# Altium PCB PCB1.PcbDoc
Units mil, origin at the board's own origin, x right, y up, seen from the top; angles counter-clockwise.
Board outline 2700 x 2100 mil, 2 copper layers (Top Layer, Bottom Layer); 10 components, 29 nets, 378 pads, 17 vias.
Unrouted connection lines stored in the file: 1.
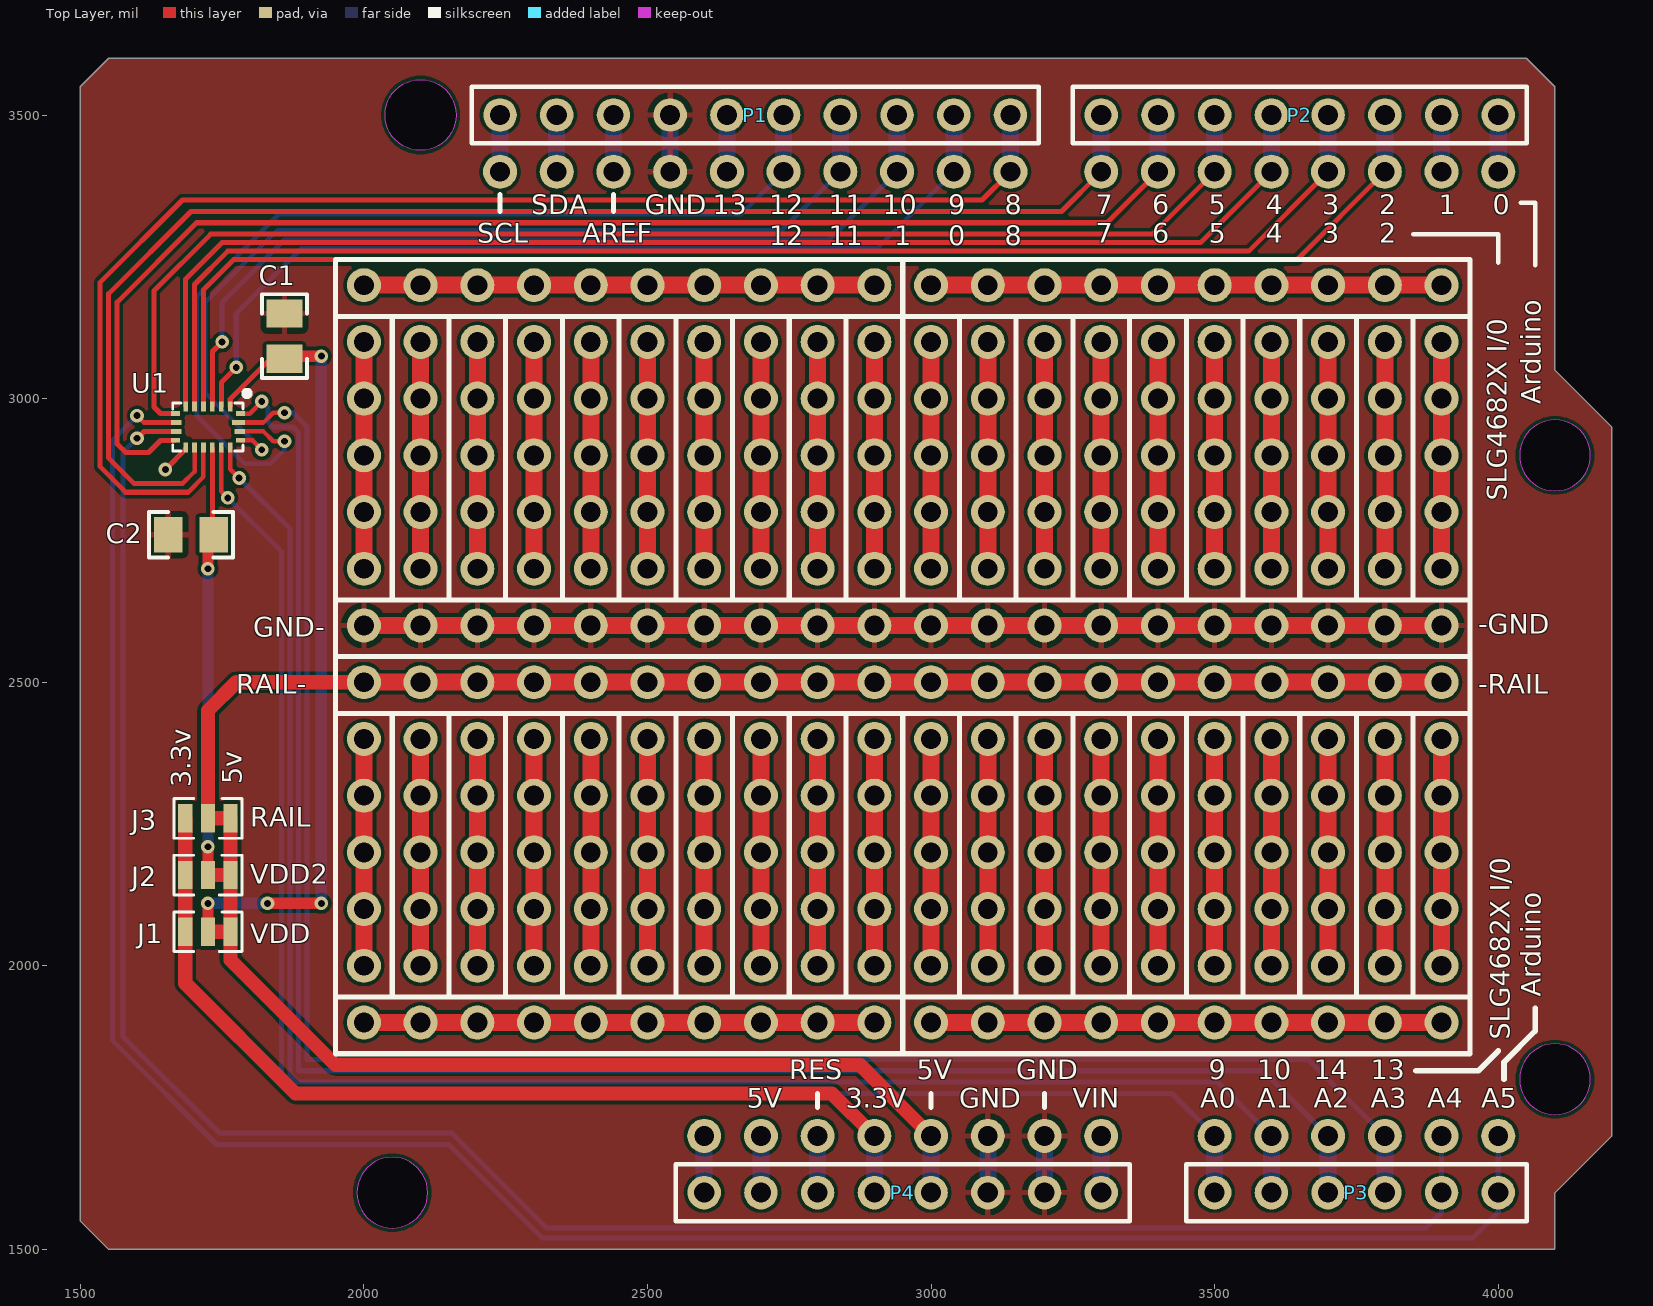
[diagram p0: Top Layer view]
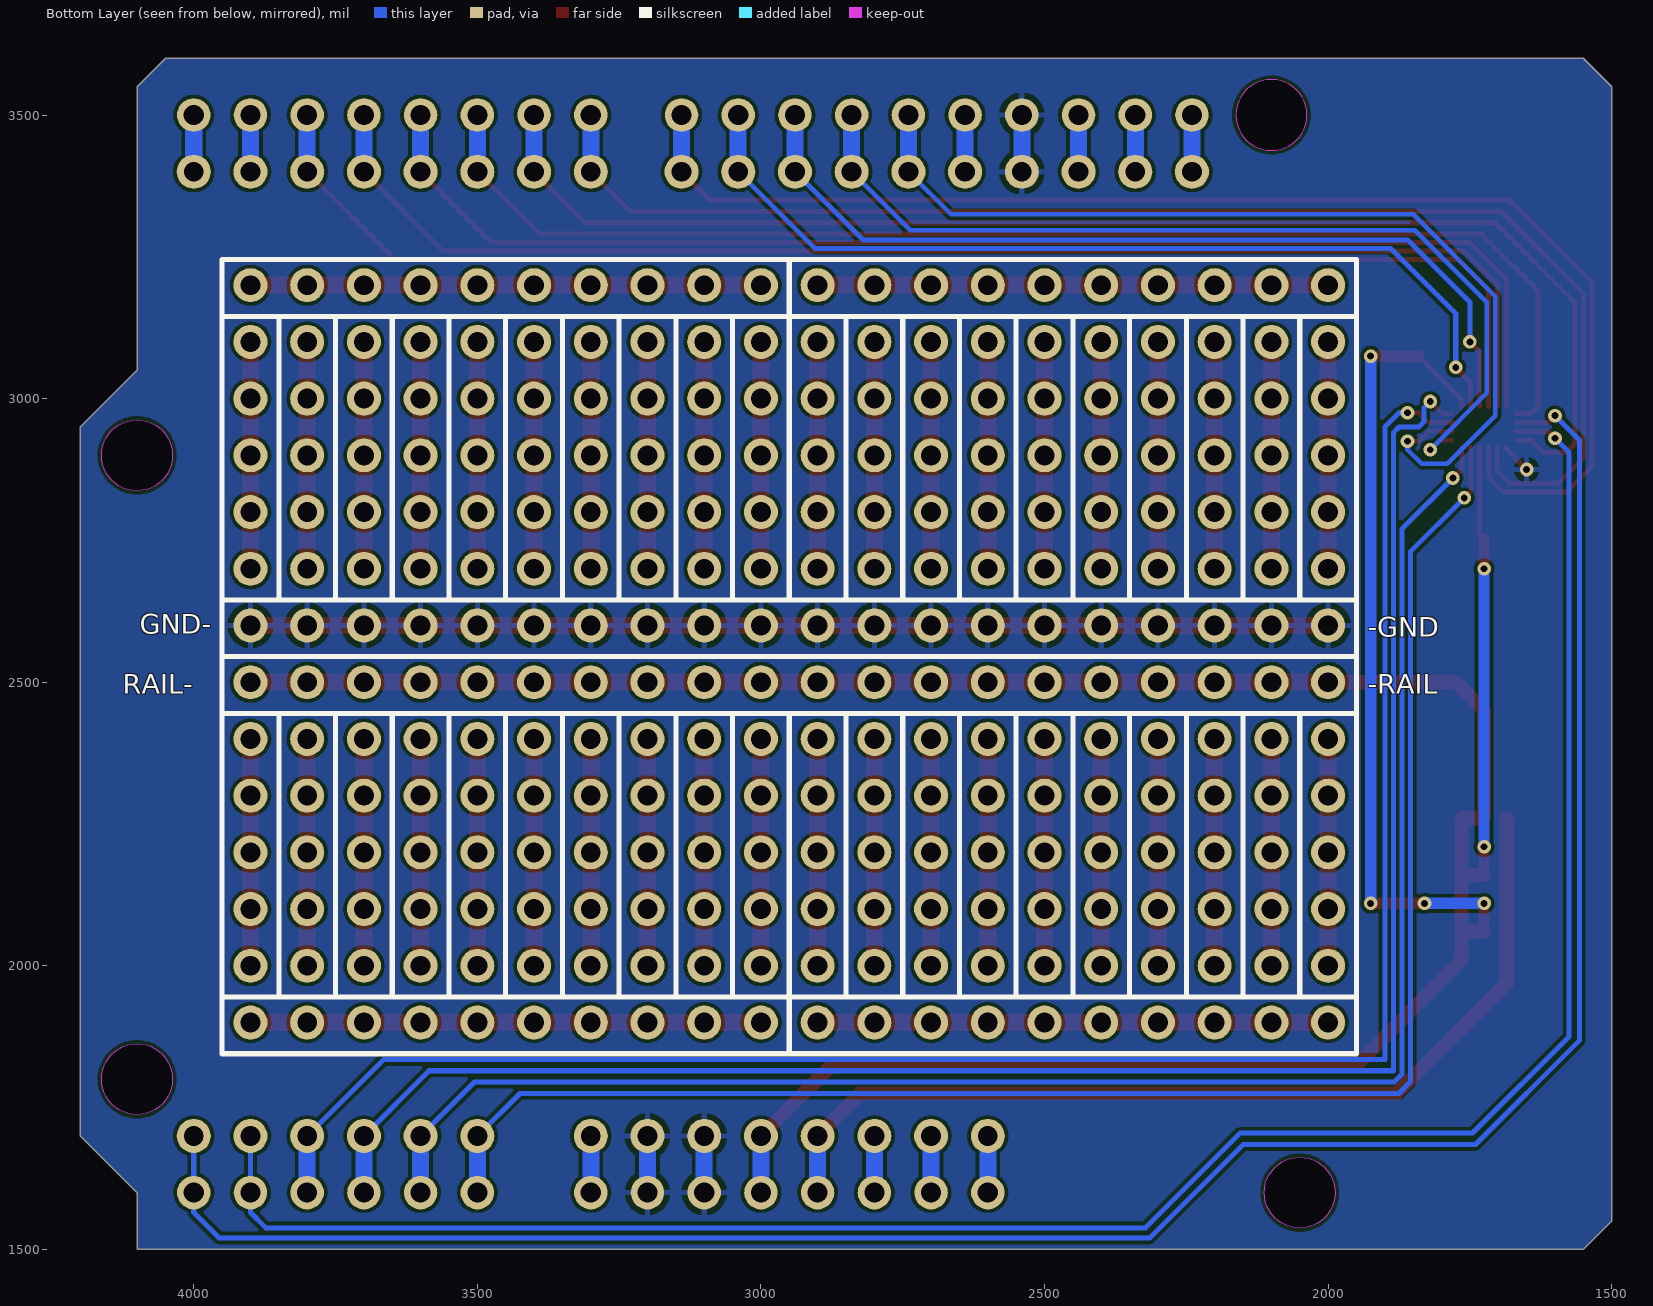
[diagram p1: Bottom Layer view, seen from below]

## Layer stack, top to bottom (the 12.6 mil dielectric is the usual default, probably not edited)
Top Solder: solder mask 0.4, Solder Resist, Dk 3.5
Top Layer: signal copper 1.4
Dielectric 1: dielectric 12.6, FR-4, Dk 4.8
Bottom Layer: signal copper 1.4
Bottom Solder: solder mask 0.4, Solder Resist, Dk 3.5

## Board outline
1550,1500 1500,1550 1500,3550 1550,3600 4050,3600 4100,3550 4100,3050 4200,2950 4200,1700 4100,1600 4100,1500
cut-out: 4037.5,1800 ccw(c4100,1800) 4100,1737.5 ccw(c4100,1800) 4162.5,1800 ccw(c4100,1800) 4100,1862.5 ccw(c4100,1800)
cut-out: 4037.5,2900 ccw(c4100,2900) 4100,2837.5 ccw(c4100,2900) 4162.5,2900 ccw(c4100,2900) 4100,2962.5 ccw(c4100,2900)
cut-out: 2100,3437.5 cw(c2100,3500) 2037.5,3500 cw(c2100,3500) 2100,3562.5 cw(c2100,3500) 2162.5,3500 cw(c2100,3500)
cut-out: 1987.5,1600 ccw(c2050,1600) 2050,1537.5 ccw(c2050,1600) 2112.5,1600 ccw(c2050,1600) 2050,1662.5 ccw(c2050,1600)

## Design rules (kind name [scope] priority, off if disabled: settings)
Clearance [All] p1: gap=6 ignorepadtopadclearanceinfootprint=FALSE
PolygonConnect [All] p1: connectstyle=Relief reliefconductorwidth=10 reliefentries=4 polygonreliefangle="90 Angle" airgapwidth=10
RoutingVias [All] p1: holewidth=12 width=24 viastyle="Through Hole" minholewidth=12 minwidth=24 maxholewidth=300 maxwidth=400
SolderMaskExpansion [All] p1: expansion=4
Width [All] p1: maxlimit=50 minlimit=6 preferedwidth=10
30 further rules are at their usual default settings.

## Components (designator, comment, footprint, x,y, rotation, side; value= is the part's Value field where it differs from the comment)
C1 "C2012X5R1H104M085AA" 0805_HV 1860,3110 r90 top value=0.1uF
C2 "C2012X5R1H104M085AA" 0805_HV 1695,2760 r180 top value=0.1uF
J1 "Jumper" JUMPER 1725,2060 r0 top net-tie
J2 "Jumper" JUMPER 1725,2160 r0 top net-tie
J3 "Jumper" JUMPER 1725,2260 r0 top net-tie
P1 "Header 10" HDR1X10 3140,3500 r180 top locked
P2 "Header 8" HDR1X8 4000,3500 r180 top locked
P3 "Header 6" HDR1X6 3500,1600 r0 top locked
P4 "Header 8" HDR1X8 2600,1600 r0 top locked
U1 "Component_1" STQFN 1725,2950 r270 top

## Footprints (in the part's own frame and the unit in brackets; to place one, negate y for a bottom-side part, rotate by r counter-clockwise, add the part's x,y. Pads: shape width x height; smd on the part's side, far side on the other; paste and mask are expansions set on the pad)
0805_HV [mil] "0805 with 30mil clearance between pads"
  rect 50x63 smd: 1(-40,0) 2(40,0)
  silkscreen extent -74,-40 74,40, body extent -43,-29 43,29, height 57
HDR1X6 [mm] "Connector; Header; 6 Position"
  round 1.5 hole 0.9: 1(0,0) 2(2.54,0) 3(5.08,0) 4(7.62,0) 5(10.16,0) 6(12.7,0)
  silkscreen extent -1.27,-1.27 13.97,1.27
HDR1X8 [mm] "Connector; Header; 8 Position"
  round 1.5 hole 0.9: 1(0,0) 2(2.54,0) 3(5.08,0) 4(7.62,0) 5(10.16,0) 6(12.7,0) 7(15.24,0) 8(17.78,0)
  silkscreen extent -1.27,-1.27 19.05,1.27
HDR1X10 [mm] "Connector; Header; 10 Position"
  round 1.5 hole 0.9: 1(0,0) 2(2.54,0) 3(5.08,0) 4(7.62,0) 5(10.16,0) 6(12.7,0) 7(15.24,0) 8(17.78,0) 9(20.32,0) 10(22.86,0)
  silkscreen extent -1.27,-1.27 24.13,1.27
JUMPER [mil]
  rect 25x50 smd: 1(-40,0) 2(0,0) 3(40,0)
  Top Layer lines w25: 0,0 40,0
  silkscreen extent -60,-35 60,35
STQFN [mm] "PACKAGE OUTLINES FOR STQFN 20L 2 MM X 3 MM 0.4P FCD"
  rect 0.465x0.21 smd: 1(-0.917,1) 2(-0.917,0.6) 3(-0.918,0.2) 4(-0.918,-0.2) 5(-0.917,-0.6) 6(-0.917,-1) 11(0.917,-1) 12(0.917,-0.6) 13(0.918,-0.2) 14(0.918,0.2) 15(0.917,0.6) 16(0.917,1)
  rect 0.21x0.39 smd: 7(-0.6,-1.455) 10(0.6,-1.455) 17(0.6,1.455) 20(-0.6,1.455)
  rect 0.21x0.465 smd: 8(-0.2,-1.418) 9(0.2,-1.418) 18(0.2,1.418)
  rect 0.21x0.565 smd: 19(-0.2,1.368)
  silkscreen extent -1.63,-1.58 1.07,1.88, body extent -1,-1.5 1,1.5, height 0.55

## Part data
C1 C2: "CAP, CERM, 0.1 µF, 50 V, +/- 20%, X5R, 0805", Cap_Case=0805, Manufacturer=TDK, Supplier Part Number 1=445-10548-1-ND, TempCo=X5R, Tolerance_%=20, Value1="0.02619 ohm", Value2=50V, ValueDisplayed=0.1µF
P1: "Header, 10-Pin"
P2 P4: "Header, 8-Pin"
P3: "Header, 6-Pin"

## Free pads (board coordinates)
  round 60 hole 35: ""(2000,1900) ""(2000,2000) ""(2000,2100) ""(2000,2200) ""(2000,2300) ""(2000,2400) ""(2000,2500) ""(2000,2600) ""(2000,2700) ""(2000,2800) ""(2000,2900) ""(2000,3000) ""(2000,3100) ""(2000,3200) ""(2100,1900) ""(2100,2000) ""(2100,2100) ""(2100,2200) ""(2100,2300) ""(2100,2400) ""(2100,2500) ""(2100,2600) ""(2100,2700) ""(2100,2800) ""(2100,2900) ""(2100,3000) ""(2100,3100) ""(2100,3200) ""(2200,1900) ""(2200,2000) ""(2200,2100) ""(2200,2200) ""(2200,2300) ""(2200,2400) ""(2200,2500) ""(2200,2600) ""(2200,2700) ""(2200,2800) ""(2200,2900) ""(2200,3000) ""(2200,3100) ""(2200,3200) ""(2240,3400) ""(2300,1900) ""(2300,2000) ""(2300,2100) ""(2300,2200) ""(2300,2300) ""(2300,2400) ""(2300,2500) ""(2300,2600) ""(2300,2700) ""(2300,2800) ""(2300,2900) ""(2300,3000) ""(2300,3100) ""(2300,3200) ""(2340,3400) ""(2400,1900) ""(2400,2000) ""(2400,2100) ""(2400,2200) ""(2400,2300) ""(2400,2400) ""(2400,2500) ""(2400,2600) ""(2400,2700) ""(2400,2800) ""(2400,2900) ""(2400,3000) ""(2400,3100) ""(2400,3200) ""(2440,3400) ""(2500,1900) ""(2500,2000) ""(2500,2100) ""(2500,2200) ""(2500,2300) ""(2500,2400) ""(2500,2500) ""(2500,2600) ""(2500,2700) ""(2500,2800) ""(2500,2900) ""(2500,3000) ""(2500,3100) ""(2500,3200) ""(2540,3400) ""(2600,1700) ""(2600,1900) ""(2600,2000) ""(2600,2100) ""(2600,2200) ""(2600,2300) ""(2600,2400) ""(2600,2500) ""(2600,2600) ""(2600,2700) ""(2600,2800) ""(2600,2900) ""(2600,3000) ""(2600,3100) ""(2600,3200) ""(2640,3400) ""(2700,1700) ""(2700,1900) ""(2700,2000) ""(2700,2100) ""(2700,2200) ""(2700,2300) ""(2700,2400) ""(2700,2500) ""(2700,2600) ""(2700,2700) ""(2700,2800) ""(2700,2900) ""(2700,3000) ""(2700,3100) ""(2700,3200) ""(2740,3400) ""(2800,1700) ""(2800,1900) ""(2800,2000) ""(2800,2100) ""(2800,2200) ""(2800,2300) ""(2800,2400) ""(2800,2500) ""(2800,2600) ""(2800,2700) ""(2800,2800) ""(2800,2900) ""(2800,3000) ""(2800,3100) ""(2800,3200) ""(2840,3400) ""(2900,1700) ""(2900,1900) ""(2900,2000) ""(2900,2100) ""(2900,2200) ""(2900,2300) ""(2900,2400) ""(2900,2500) ""(2900,2600) ""(2900,2700) ""(2900,2800) ""(2900,2900) ""(2900,3000) ""(2900,3100) ""(2900,3200) ""(2940,3400) ""(3000,1700) ""(3000,1900) ""(3000,1900) ""(3000,2000) ""(3000,2100) ""(3000,2200) ""(3000,2300) ""(3000,2400) ""(3000,2500) ""(3000,2600) ""(3000,2700) ""(3000,2800) ""(3000,2900) ""(3000,3000) ""(3000,3100) ""(3000,3200) ""(3040,3400) ""(3100,1700) ""(3100,1900) ""(3100,2000) ""(3100,2100) ""(3100,2200) ""(3100,2300) ""(3100,2400) ""(3100,2500) ""(3100,2600) ""(3100,2700) ""(3100,2800) ""(3100,2900) ""(3100,3000) ""(3100,3100) ""(3100,3200) ""(3140,3400) ""(3200,1700) ""(3200,1900) ""(3200,2000) ""(3200,2100) ""(3200,2200) ""(3200,2300) ""(3200,2400) ""(3200,2500) ""(3200,2600) ""(3200,2700) ""(3200,2800) ""(3200,2900) ""(3200,3000) ""(3200,3100) ""(3200,3200) ""(3300,1700) ""(3300,1900) ""(3300,2000) ""(3300,2100) ""(3300,2200) ""(3300,2300) ""(3300,2400) ""(3300,2500) ""(3300,2600) ""(3300,2700) ""(3300,2800) ""(3300,2900) ""(3300,3000) ""(3300,3100) ""(3300,3200) ""(3300,3400) ""(3400,1900) ""(3400,2000) ""(3400,2100) ""(3400,2200) ""(3400,2300) ""(3400,2400) ""(3400,2500) ""(3400,2600) ""(3400,2700) ""(3400,2800) ""(3400,2900) ""(3400,3000) ""(3400,3100) ""(3400,3200) ""(3400,3400) ""(3500,1700) ""(3500,1900) ""(3500,2000) ""(3500,2100) ""(3500,2200) ""(3500,2300) ""(3500,2400) ""(3500,2500) ""(3500,2600) ""(3500,2700) ""(3500,2800) ""(3500,2900) ""(3500,3000) ""(3500,3100) ""(3500,3200) ""(3500,3400) ""(3600,1700) ""(3600,1900) ""(3600,2000) ""(3600,2100) ""(3600,2200) ""(3600,2300) ""(3600,2400) ""(3600,2500) ""(3600,2600) ""(3600,2700) ""(3600,2800) ""(3600,2900) ""(3600,3000) ""(3600,3100) ""(3600,3200) ""(3600,3400) ""(3700,1700) ""(3700,1900) ""(3700,2000) ""(3700,2100) ""(3700,2200) ""(3700,2300) ""(3700,2400) ""(3700,2500) ""(3700,2600) ""(3700,2700) ""(3700,2800) ""(3700,2900) ""(3700,3000) ""(3700,3100) ""(3700,3200) ""(3700,3400) ""(3800,1700) ""(3800,1900) ""(3800,2000) ""(3800,2100) ""(3800,2200) ""(3800,2300) ""(3800,2400) ""(3800,2500) ""(3800,2600) ""(3800,2700) ""(3800,2800) ""(3800,2900) ""(3800,3000) ""(3800,3100) ""(3800,3200) ""(3800,3400) ""(3900,1700) ""(3900,1900) ""(3900,2000) ""(3900,2100) ""(3900,2200) ""(3900,2300) ""(3900,2400) ""(3900,2500) ""(3900,2600) ""(3900,2700) ""(3900,2800) ""(3900,2900) ""(3900,3000) ""(3900,3100) ""(3900,3200) ""(3900,3400) ""(4000,1700) ""(4000,3400)

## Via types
v1: diameter 24, hole 12, Top Layer to Bottom Layer, tented both sides, 17 vias

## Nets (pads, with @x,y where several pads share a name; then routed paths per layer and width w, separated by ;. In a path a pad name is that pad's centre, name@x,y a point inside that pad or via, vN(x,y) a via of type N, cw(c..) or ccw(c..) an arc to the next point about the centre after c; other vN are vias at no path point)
3.3V: J1.1 J2.1 J3.1 P4.4 pad.@2900,1700 | length 1717.3
  Top Layer w25: J3.1 1685,2200 J2.1 J1.1 1685,1969.29 1879.29,1775 2825,1775 pad.@2900,1700
  Bottom Layer w30: P4.4 pad.@2900,1700
5V: J1.3 J2.3 J3.3 P4.2 P4.5 pad.@2700,1700 pad.@3000,1700 | length 1813.4
  Top Layer w25: J3.3 1765,2200 J2.3 J1.3 1765,2010 1950,1825 2875,1825 pad.@3000,1700
  Bottom Layer w30: P4.2 pad.@2700,1700 ; P4.5 pad.@3000,1700
AD0: P3.1 pad.@3500,1700 U1.15 | length 2947.3
  Top Layer w8: U1.15 1748.62,2836.38 v1(1760,2825)
  Bottom Layer w9: v1(1760,2825) 1855,2730 1855,1795 1875,1775 3425,1775 pad.@3500,1700
  Bottom Layer w30: P3.1 pad.@3500,1700
AD1: P3.2 pad.@3600,1700 U1.16 | length 3024.2
  Top Layer w8: U1.16 1764.37,2875.63 v1(1780,2860)
  Bottom Layer w9: v1(1780,2860) 1870,2770 1870,1808.28 1883.28,1795 3505,1795 pad.@3600,1700
  Bottom Layer w30: P3.2 pad.@3600,1700
AD2: P3.3 pad.@3700,1700 U1.20 | length 3239.5
  Top Layer w8: U1.20 1798.62,2973.62 v1(1820,2995)
  Bottom Layer w9: v1@1815,2990 1825,2990 1831.25,2983.75 1831.25,2958.75 1840,2950 1875,2950 1885,2940 1885,1815 3585,1815 pad.@3700,1700
  Bottom Layer w30: P3.3 pad.@3700,1700
AD3: P3.4 pad.@3800,1700 U1.19 | length 3309.6
  Top Layer w8: U1.19 1822.87,2957.87 1840,2975 v1(1860,2975)
  Bottom Layer w9: v1(1860,2975) 1875,2975 1900,2950 1900,1834.85 3665.15,1834.85 pad.@3800,1700
  Bottom Layer w30: P3.4 pad.@3800,1700
AD4/SDA: P3.5 pad.@3900,1700 U1.9 | length 3750.1
  Top Layer w9: v1(1600,2930) 1612.13,2942.13 U1.9
  Bottom Layer w9: v1(1600,2930) 1575,2905 1575,1875.46 1745.46,1705 2155,1705 2322,1538 3873,1538 3900,1565 P3.5 pad.@3900,1700
AD5/SCL: P3.6 pad.@4000,1700 U1.8 | length 3934.8
  Top Layer w8: v1(1600,2970) 1612.13,2957.87 U1.8
  Bottom Layer w9: v1(1600,2970) 1557,2927 1557,1868 1740,1685 2149.54,1685 2314.54,1520 3955,1520 4000,1565 P3.6 pad.@4000,1700
AREF: P1.8 pad.@2440,3400 | length 100
  Bottom Layer w30: pad.@2440,3400 P1.8
BreakOutRail: J3.2 pad.@2000,2500 pad.@2100,2500 pad.@2200,2500 pad.@2300,2500 pad.@2400,2500 pad.@2500,2500 pad.@2600,2500 pad.@2700,2500 pad.@2800,2500 pad.@2900,2500 pad.@3000,2500 pad.@3100,2500 pad.@3200,2500 pad.@3300,2500 pad.@3400,2500 pad.@3500,2500 pad.@3600,2500 pad.@3700,2500 pad.@3800,2500 pad.@3900,2500 | length 2385.7
  Top Layer w25: J3.2 1725,2450 1775,2500 pad.@2000,2500
  Top Layer w30: pad.@2000,2500 2100,2500 2200,2500 2300,2500 2400,2500 2500,2500 2600,2500 2700,2500 2800,2500 2900,2500 3000,2500 3100,2500 3200,2500 3300,2500 3400,2500 3500,2500 3600,2500 3700,2500 3800,2500 pad.@3900,2500
GND: C1.2 C2.2 P1.7 P4.6 P4.7 pad.@2000,2600 pad.@2100,2600 pad.@2200,2600 pad.@2300,2600 pad.@2400,2600 pad.@2500,2600 pad.@2540,3400 pad.@2600,2600 pad.@2700,2600 pad.@2800,2600 pad.@2900,2600 pad.@3000,2600 pad.@3100,1700 pad.@3100,2600 pad.@3200,1700 pad.@3200,2600 pad.@3300,2600 pad.@3400,2600 pad.@3500,2600 pad.@3600,2600 pad.@3700,2600 pad.@3800,2600 pad.@3900,2600 U1.11 | length 2253.6
  Top Layer w9: v1(1650,2875) 1685.63,2910.63 U1.11
  Top Layer w30: pad.@2000,2600 2100,2600 2200,2600 2300,2600 2400,2600 2500,2600 2600,2600 2700,2600 2800,2600 2900,2600 3000,2600 3100,2600 3200,2600 3300,2600 3400,2600 3500,2600 3600,2600 3700,2600 3800,2600 pad.@3900,2600
  Bottom Layer w30: pad.@2540,3400 P1.7 ; P4.6 pad.@3100,1700 ; P4.7 pad.@3200,1700
IO2: P2.3 pad.@3800,3400 U1.4 | length 2475
  Top Layer w9: U1.4 1717.13,3192.13 1770,3245 3645,3245 pad.@3800,3400
  Bottom Layer w30: pad.@3800,3400 P2.3
IO3: P2.4 pad.@3700,3400 U1.5 | length 2396.1
  Top Layer w9: U1.5 1701.38,3201.38 1760,3260 3560,3260 pad.@3700,3400
  Bottom Layer w30: pad.@3700,3400 P2.4
IO4: P2.5 pad.@3600,3400 U1.6 | length 2317.3
  Top Layer w9: U1.6 1685.63,3210.63 1750,3275 3475,3275 pad.@3600,3400
  Bottom Layer w30: pad.@3600,3400 P2.5
IO5: P2.6 pad.@3500,3400 U1.7 | length 2304.4
  Top Layer w9: U1.7 1641.38,2973.62 1630,2985 1630,3190 1730,3290 3390,3290 pad.@3500,3400
  Bottom Layer w30: pad.@3500,3400 P2.6
IO6: P2.7 pad.@3400,3400 U1.10 | length 2398.1
  Top Layer w9: U1.10 1641.38,2926.38 1620,2905 1580,2905 1565,2920 1565,3170 1705,3310 3310,3310 pad.@3400,3400
  Bottom Layer w30: pad.@3400,3400 P2.7
IO7: P2.8 pad.@3300,3400 U1.12 | length 2450.4
  Top Layer w8: 1680,2850 1701.38,2871.38 U1.12
  Top Layer w9: 1680,2850 1595,2850 1550,2895 1550,3185 1695,3330 3230,3330 pad.@3300,3400
  Bottom Layer w30: pad.@3300,3400 P2.8
IO8: P1.1 pad.@3140,3400 U1.13 | length 2374.5
  Top Layer w8: 1690,2835 1717.13,2862.13 U1.13
  Top Layer w9: 1690,2835 1580,2835 1535,2880 1535,3205 1680,3350 3090,3350 pad.@3140,3400
  Bottom Layer w30: pad.@3140,3400 P1.1
IO9: P1.2 pad.@3040,3400 U1.2 | length 1643.4
  Top Layer w9: U1.2 1748.62,3028.62 v1(1775,3055)
  Bottom Layer w9: v1(1775,3055) 1775,3150 1890,3265 2905,3265 pad.@3040,3400
  Bottom Layer w30: pad.@3040,3400 P1.2
MISO/IO12: P1.5 pad.@2740,3400 U1.18 | length 1738
  Top Layer w8: U1.18 1822.87,2942.13 1840,2925 v1(1860,2925)
  Bottom Layer w8: v1(1860,2925) 1860,2910 1835,2885 1790,2885 1705,2970 1705,3180 1850,3325 2665,3325 pad.@2740,3400
  Bottom Layer w30: pad.@2740,3400 P1.5
MOSI/IO11: P1.4 pad.@2840,3400 U1.17 | length 1661.2
  Top Layer w8: U1.17 1803.62,2926.38 v1(1820,2910)
  Bottom Layer w8: v1(1820,2910) 1720,3010 1720,3170 1847,3297 2737,3297 pad.@2840,3400
  Bottom Layer w30: pad.@2840,3400 P1.4
NetC1_1: C1.1 J1.2 U1.1 | length 1420.2
  Top Layer w9: U1.1 1764.37,2999.37 C1.1@1840,3075
  Top Layer w20: J1.2 v1(1725,2110) ; v1(1830,2110) v1(1925,2110) ; C1.1@1840,3075 v1(1925,3075)
  Bottom Layer w20: v1(1725,2110) v1(1830,2110) ; v1(1925,2110) v1(1925,3075)
NetC2_1: C2.1 J2.2 U1.14 | length 757.1
  Top Layer w9: C2.1@1725,2752.13 1732.87,2760 U1.14
  Top Layer w20: J2.2 v1(1725,2210) ; v1(1725,2700) C2.1@1725,2752.13
  Bottom Layer w20: v1(1725,2210) v1(1725,2700)
RESET: P4.3 pad.@2800,1700 | length 100
  Bottom Layer w30: P4.3 pad.@2800,1700
RX/IO0: P2.1 pad.@4000,3400 | length 100
  Bottom Layer w30: pad.@4000,3400 P2.1
SCK/IO13: P1.6 pad.@2640,3400 | length 100
  Bottom Layer w30: pad.@2640,3400 P1.6
SS/IO10: P1.3 pad.@2940,3400 U1.3 | length 1576.2
  Top Layer w9: U1.3 1732.87,3082.87 v1(1750,3100)
  Bottom Layer w9: v1(1750,3100) 1750,3170 1860,3280 2820,3280 pad.@2940,3400
  Bottom Layer w30: pad.@2940,3400 P1.3
TX/IO1: P2.2 pad.@3900,3400 | length 100
  Bottom Layer w30: pad.@3900,3400 P2.2
Vin: P4.8 pad.@3300,1700 | length 100
  Bottom Layer w30: P4.8 pad.@3300,1700
pads on no net: P1.9 P1.10 P4.1
copper on no net: | length 19900
  Top Layer w30: 2000,1900 2900,1900 ; 2000,2000 2000,2400 ; 2000,2700 2000,3100 ; 2000,3200 2900,3200 ; 2100,2000 2100,2400 ; 2100,2700 2100,3100 ; 2200,2000 2200,2400 ; 2200,2700 2200,3100 ; 2300,2000 2300,2400 ; 2300,2700 2300,3100 ; 2400,2000 2400,2400 ; 2400,2700 2400,3100 ; 2500,2000 2500,2400 ; 2500,2700 2500,3100 ; 2600,2000 2600,2400 ; 2600,2700 2600,3100 ; 2700,2000 2700,2400 ; 2700,2700 2700,3100 ; 2800,2000 2800,2400 ; 2800,2700 2800,3100 ; 2900,2000 2900,2400 ; 2900,2700 2900,3100 ; 3000,1900 3900,1900 ; 3000,2000 3000,2400 ; 3000,2700 3000,3100 ; 3000,3200 3900,3200 ; 3100,2000 3100,2400 ; 3100,2700 3100,3100 ; 3200,2000 3200,2400 ; 3200,2700 3200,3100 ; 3300,2000 3300,2400 ; 3300,2700 3300,3100 ; 3400,2000 3400,2400 ; 3400,2700 3400,3100 ; 3500,2000 3500,2400 ; 3500,2700 3500,3100 ; 3600,2000 3600,2400 ; 3600,2700 3600,3100 ; 3700,2000 3700,2400 ; 3700,2700 3700,3100 ; 3800,2000 3800,2400 ; 3800,2700 3800,3100 ; 3900,2000 3900,2400 ; 3900,2700 3900,3100
  Bottom Layer w30: 2240,3400 2240,3500 ; 2340,3400 2340,3500 ; 2600,1600 2600,1700

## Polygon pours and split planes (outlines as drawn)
GND on Top Layer "Top Layer-gnd" (solid, pour order 0): 1550,1500 1500,1550 1500,3550 1550,3600 4050,3600 4100,3550 4100,3050 4200,2950 4200,1700 4100,1600 4100,1500
GND on Bottom Layer "bottom Layer-gnd" (solid, pour order 1): 1550,1500 1500,1550 1500,3550 1550,3600 4050,3600 4100,3550 4100,3050 4200,2950 4200,1700 4100,1600 4100,1500

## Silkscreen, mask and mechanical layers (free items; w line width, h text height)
Top Overlay:
  lines w8: 3850,3290 4000,3290 4000,3240 ; 4040,3345 4065,3345 4065,3235
  lines w9: 1950,1945 3950,1945 ; 1950,2445 3950,2445 ; 1950,2545 3950,2545 ; 1950,2645 3950,2645 ; 1950,3145 3950,3145 ; 2050,1945 2050,2445 ; 2050,2645 2050,3145 ; 2150,1945 2150,2445 ; 2150,2645 2150,3145 ; 2240,3330 2240,3360 ; 2250,1945 2250,2445 ; 2250,2645 2250,3145 ; 2350,1945 2350,2445 ; 2350,2645 2350,3145 ; 2440,3330 2440,3360 ; 2450,1945 2450,2445 ; 2450,2645 2450,3145 ; 2550,1945 2550,2445 ; 2550,2645 2550,3145 ; 2650,1945 2650,2445 ; 2650,2645 2650,3145 ; 2750,1945 2750,2445 ; 2750,2645 2750,3145 ; 2800,1750 2800,1775 ; 2850,1945 2850,2445 ; 2850,2645 2850,3145 ; 2950,1845 2950,2445 ; 2950,2645 2950,3245 ; 3000,1750 3000,1775 ; 3050,1945 3050,2445 ; 3050,2645 3050,3145 ; 3150,1945 3150,2445 ; 3150,2645 3150,3145 ; 3200,1750 3200,1775 ; 3250,1945 3250,2445 ; 3250,2645 3250,3145 ; 3350,1945 3350,2445 ; 3350,2645 3350,3145 ; 3450,1945 3450,2445 ; 3450,2645 3450,3145 ; 3550,1945 3550,2445 ; 3550,2645 3550,3145 ; 3650,1945 3650,2445 ; 3650,2645 3650,3145 ; 3750,1945 3750,2445 ; 3750,2645 3750,3145 ; 3850,1945 3850,2445 ; 3850,2645 3850,3145 ; 1950,1845 1950,3245 3950,3245 3950,1845 1950,1845
  lines w10: 3855,1815 3965,1815 4000,1850 ; 4010,1800 4010,1830 4065,1885 4065,1925
  text "SDA" at 2295,3325 h35
  text "GND" at 2495,3325 h35
  text "13" at 2615,3325 h35
  text "12" at 2715,3325 h35
  text "11" at 2820,3325 h35
  text "10" at 2915,3325 h35
  text "9" at 3030,3325 h35
  text "8" at 3130,3325 h35
  text "7" at 3290,3325 h35
  text "6" at 3390,3325 h35
  text "5" at 3490,3325 h35
  text "4" at 3590,3325 h35
  text "3" at 3690,3325 h35
  text "2" at 3790,3325 h35
  text "1" at 3895,3325 h35
  text "0" at 3990,3325 h35
  text "SCL" at 2200,3275 h35
  text "AREF" at 2385,3275 h35
  text "7" at 3290,3275 h35
  text "6" at 3390,3275 h35
  text "5" at 3490,3275 h35
  text "4" at 3590,3275 h35
  text "3" at 3690,3275 h35
  text "2" at 3790,3275 h35
  text "12" at 2715,3270 h35
  text "11" at 2820,3270 h35
  text "1" at 2935,3270 h35
  text "0" at 3030,3270 h35
  text "8" at 3130,3270 h35
  text "Arduino" at 4075,2990 h35 r90
  text "SLG4682X I/0" at 4015,2820 h35 r90
  text "-GND" at 3965,2585 h35
  text "GND-" at 1805,2580 h35
  text "RAIL-" at 1775,2480 h35
  text "-RAIL" at 3965,2480 h35
  text "5v" at 1785,2320 h35 r90
  text "3.3v" at 1695,2315 h35 r90
  text "RAIL" at 1800,2245 h35
  text "VDD2" at 1800,2145 h35
  text "VDD" at 1800,2040 h35
  text "Arduino" at 4075,1945 h35 r90
  text "SLG4682X I/0" at 4020,1870 h35 r90
  text "RES" at 2750,1800 h35
  text "5V" at 2975,1800 h35
  text "GND" at 3150,1800 h35
  text "9" at 3490,1800 h35
  text "10" at 3575,1800 h35
  text "14" at 3675,1800 h35
  text "13" at 3775,1800 h35
  text "5V" at 2675,1750 h35
  text "3.3V" at 2850,1750 h35
  text "GND" at 3050,1750 h35
  text "VIN" at 3250,1750 h35
  text "A0" at 3475,1750 h35
  text "A1" at 3575,1750 h35
  text "A2" at 3675,1750 h35
  text "A3" at 3775,1750 h35
  text "A4" at 3875,1750 h35
  text "A5" at 3970,1750 h35
Bottom Overlay:
  lines w9: 1950,1945 3950,1945 ; 1950,2445 3950,2445 ; 1950,2545 3950,2545 ; 1950,2645 3950,2645 ; 1950,3145 3950,3145 ; 2050,1945 2050,2445 ; 2050,2645 2050,3145 ; 2150,1945 2150,2445 ; 2150,2645 2150,3145 ; 2250,1945 2250,2445 ; 2250,2645 2250,3145 ; 2350,1945 2350,2445 ; 2350,2645 2350,3145 ; 2450,1945 2450,2445 ; 2450,2645 2450,3145 ; 2550,1945 2550,2445 ; 2550,2645 2550,3145 ; 2650,1945 2650,2445 ; 2650,2645 2650,3145 ; 2750,1945 2750,2445 ; 2750,2645 2750,3145 ; 2850,1945 2850,2445 ; 2850,2645 2850,3145 ; 2950,1845 2950,2445 ; 2950,2645 2950,3245 ; 3050,1945 3050,2445 ; 3050,2645 3050,3145 ; 3150,1945 3150,2445 ; 3150,2645 3150,3145 ; 3250,1945 3250,2445 ; 3250,2645 3250,3145 ; 3350,1945 3350,2445 ; 3350,2645 3350,3145 ; 3450,1945 3450,2445 ; 3450,2645 3450,3145 ; 3550,1945 3550,2445 ; 3550,2645 3550,3145 ; 3650,1945 3650,2445 ; 3650,2645 3650,3145 ; 3750,1945 3750,2445 ; 3750,2645 3750,3145 ; 3850,1945 3850,2445 ; 3850,2645 3850,3145 ; 1950,1845 1950,3245 3950,3245 3950,1845 1950,1845
  text "GND-" at 4095,2585 h35
  text "-GND" at 1930,2580 h35
  text "-RAIL" at 1930,2480 h35
  text "RAIL-" at 4125,2480 h35
Mechanical 1:
  the board outline again, w9

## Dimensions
1500,1550 to 4200,1700 on Mechanical 1
4100,1500 to 4050,3600 on Mechanical 1
1500,3550 to 4000,3500 on Mechanical 1
1500,3550 to 3140,3500 on Mechanical 1
1500,1550 to 3300,1600 on Mechanical 1
1500,1550 to 4000,1600 on Mechanical 1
